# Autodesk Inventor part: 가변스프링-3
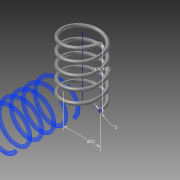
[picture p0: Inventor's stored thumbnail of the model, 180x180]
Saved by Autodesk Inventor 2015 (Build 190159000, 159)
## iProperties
Created: 2016-01
Part Number: 가변스프링-3
Material: 스테인레스 스틸
Document SubType Name: Modeling
Designer: 601-23
Density: 8 g/cm^3
Appearance: 반연마
Mass: 8.58406 g
Surface Area: 21.7283 cm^2
Volume: 1.07301 cm^3
Author: 601-23
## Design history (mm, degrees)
sketch "스케치1"
  geometry: L1 (0, 0)-(11, 0); L2 (11, 0)-(11, 36.411); L3 (11, 36.411)-(0, 36.411); L4 (0, 36.411)-(0, 0); C1 r 1 at (11, 0)
  constraints: 8 end point, 2 parallel, 1 centre point, 1 coincident, 1 horizontal, 1 perpendicular
  dimensions: "d0" = 36.4112 distance of L1.end L2.end (derived); "d1" = 22 diameter of L2 L4; "d2" = 2 diameter of C1
feature "코일1" sketch "스케치1" pitch "d3" = 5; turns "d5" = 5; dims "d4" = 36.4112 (= d0), "d6" = 0, angle "d7" = 90 deg, angle "d8" = 90 deg, "d9" = 0, "d10" = 0
node "작업 평면1"
node "작업 평면2"
sketch "스케치2"
  geometry: L1 (1, 0)-(-1, 0) reference; 1 further point
  constraints: 1 horizontal alignment
extrude "돌출1" cut sketch "스케치2" stored distance "d13" = 10; taper "d14" = 0 deg
sketch "스케치3"
  geometry: L1 (10, 0)-(12, 0) reference; 1 further point
  constraints: 1 horizontal alignment
extrude "돌출2" cut sketch "스케치3" stored distance "d15" = 10; taper "d16" = 0 deg
node "솔리드1"
node "절단 모서리 투영1"
node "절단 모서리 투영2"
other parameters: "d11" = 90 deg, "d12" = 90 deg
